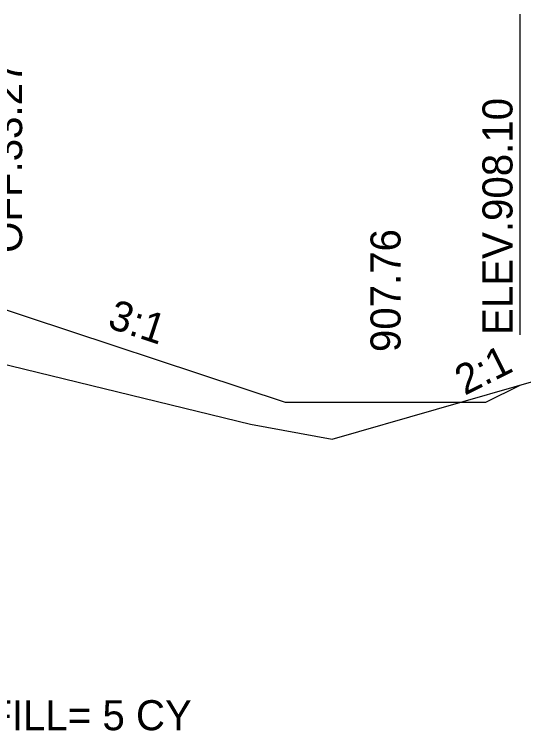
# Model space of a CAD drawing. Extents: x -4 to 359, y 0 to 1436.
# Drawn here: x 286.36 to 296.53, y 1276.17 to 1290.46 of the extents above; entities that cross this region are included whole.
import ezdxf

# ---------------------------------------------------------------- set-up
doc = ezdxf.new("R2010")
doc.units = 0
for name, color, linetype in [('XS-Existing surface-ground', 7, 'Continuous'), ('XS-Proposed surface-ground', 7, 'Continuous'), ('XS-Text-ditch slope', 7, 'Continuous'), ('XS-Text-earthwork labels', 7, 'Continuous'), ('XS-Text-profile report', 7, 'Continuous'), ('XS-Text-shoulder elevation', 7, 'Continuous'), ('XS-Text-tie elevation', 7, 'Continuous'), ('XS-Text-tie offset', 7, 'Continuous')]:
    doc.layers.add(name, color=color, linetype=linetype)

msp = doc.modelspace()

# ---------------------------------------------------------------- linework, layer by layer
at = {"layer": 'XS-Existing surface-ground'}
for p, q in [((292.705, 1281.982), (310.44, 1287.1)), ((284.572, 1283.867), (291.075, 1282.286)), ((291.075, 1282.286), (292.705, 1281.982))]:
    msp.add_line(p, q, dxfattribs=at)
at = {"layer": 'XS-Proposed surface-ground'}
msp.add_lwpolyline([(285.771, 1284.702), (291.771, 1282.722), (295.771, 1282.722), (296.455, 1283.064)], dxfattribs=at)
at = {"layer": 'XS-Text-tie offset'}
msp.add_line((296.455, 1284.064), (296.455, 1290.462), dxfattribs=at)

# ---------------------------------------------------------------- texts
at = {"layer": 'XS-Text-ditch slope'}
for s, rotation, p in [('3:1', 341.7371, (288.2, 1284.216)), ('2:1', 26.5651, (295.352, 1282.848))]:
    msp.add_text(s, height=0.6, rotation=rotation, dxfattribs=at).set_placement(p)
at = {"layer": 'XS-Text-earthwork labels'}
msp.add_text('FILL= 5 CY           ', height=0.6, dxfattribs=at).set_placement((285.826, 1276.175))
at = {"layer": 'XS-Text-profile report'}
for s, p in [('Rt_Agg_Layer_1_B13', (289.251, 1283.548)), ('Dtch_Bkslp_1_T', (296.443, 1283.063)), ('Dtch_Frslp_1_B', (291.759, 1282.721)), ('Dtch_Bkslp_1_B', (295.759, 1282.721))]:
    msp.add_text(s, height=0.00167, dxfattribs=at).set_placement(p)
at = {"layer": 'XS-Text-shoulder elevation'}
msp.add_text('OFF.33.27', height=0.6, rotation=90, dxfattribs=at).set_placement((286.521, 1285.702))
at = {"layer": 'XS-Text-tie elevation'}
for s, p in [('ELEV.908.10', (296.305, 1284.064)), ('907.76', (294.071, 1283.722))]:
    msp.add_text(s, height=0.6, rotation=90, dxfattribs=at).set_placement(p)

doc.saveas('drawing.dxf')
